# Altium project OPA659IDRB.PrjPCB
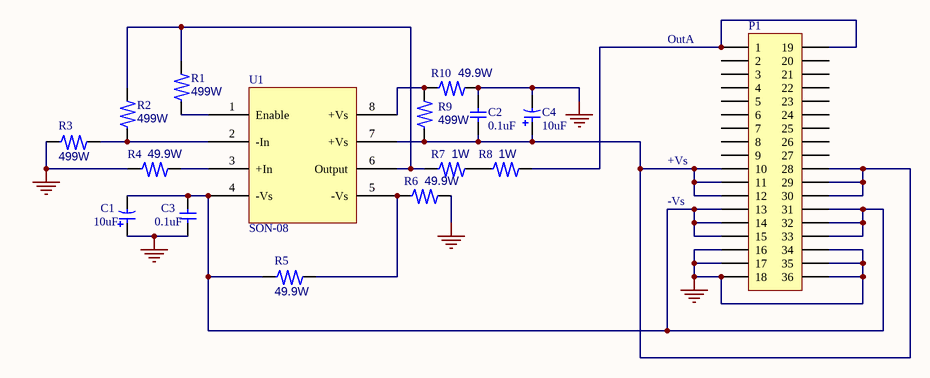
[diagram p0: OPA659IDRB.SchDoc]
1 sheet, 16 parts. Net scope: global (net labels, ports and power ports of the same name join across sheets).
Board file: OPA659IDRB.PcbDoc

## Sheet OPA659IDRB.SchDoc: OPA659IDRB Thermal  Impedance Board
size A; Date: 4-30-2007; CompanyName: Texas Instruments, Inc.; DrawnBy: Phung Luong; Engineer: Brian Lenharth; Address1: Texas Instruments; Address2: 6730 S. Tucson Blvd.; Address3: Tucson, AZ 85718; Address4: U.S.A.; DocumentNumber: PR1699; Revision: A; SheetNumber: 1; SheetTotal: 1; PageSetup: Record=PageOptions|CenterHorizontal=True|CenterVertical=True|PrintScale=1.05|XCorrection=1.00|YCorrection=1.00|PrintKind=2|BorderSize=5000000|LeftOffset=0|BottomOffset=0|Orientation=2|PaperLength=1000|PaperWidth=1000|Scale=100|PaperSource=7|PrintQuality=-4|MediaType=1|DitherType=10|PaperKind=A4|PrintScaleMode=1

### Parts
C1  10uF  [1206 (Pol)]
C2  0.1uF  [0603]
C3  0.1uF  [0603]
C4  10uF  [1206 (Pol)]
P1  (no value)  [DIP-40]
R1  499W  [0603]
R2  499W  [0603]
R3  499W  [0603]
R4  49.9W  [0603]
R5  49.9W  [0603]
R6  49.9W  [0603]
R7  1W  [0805]
R8  1W  [0805]
R9  499W  [0603]
R10  49.9W  [0402]
U1  SON-08  [QFN 3x3 (8pin) DRB]

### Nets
GND: C1.1 C2.2 C3.2 C4.2 P1.16 P1.17 P1.18 P1.34 P1.35 P1.36 R3.2 R4.2 R6.1 R10.1
NetC1_2: C1.2 C3.1 P1.13 P1.14 P1.15 P1.31 P1.32 P1.33 R5.2 U1.4(-Vs)
NetC2_1: C2.1 C4.1 P1.10 P1.11 P1.12 P1.28 P1.29 P1.30 R9.2 U1.7(+Vs)
NetP1_1: P1.1 P1.19 R8.1
NetR1_1: R1.1 R2.1 R7.2 U1.6(Output)
NetR1_2: R1.2 U1.1(Enable)
NetR2_2: R2.2 R3.1 U1.2(-In)
NetR4_1: R4.1 U1.3(+In)
NetR5_1: R5.1 R6.2 U1.5(-Vs)
NetR7_1: R7.1 R8.2
NetR9_1: R9.1 R10.2 U1.8(+Vs)

Not connected (* = marked no-connect by the designer): P1 2 3 4 5 6 7 8 9 20 21 22 23 24 25 26 27

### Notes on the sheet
- OutA
- +Vs
- -Vs

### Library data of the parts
C1 C4 = CAP (Polarized SM)
C2 C3 = CAP
P1 = MHDR2X18: Header, 18-Pin, Dual row
R1-R10 = RES (SM)
U1 = MSOP-08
